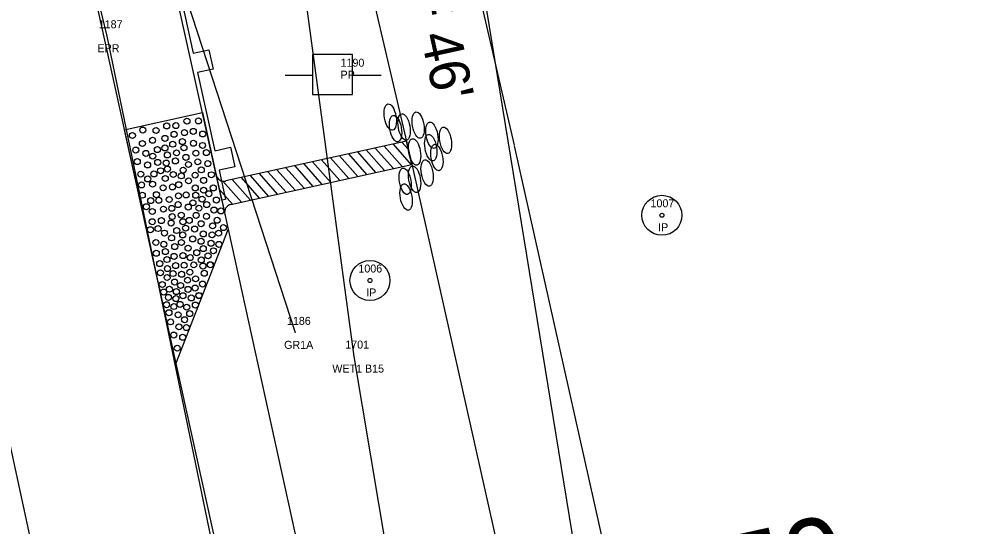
# Model space of a CAD drawing. Extents: x 2521558 to 2525396, y 882711 to 887632.
# Drawn here: x 2523806.5 to 2523924.8, y 884989.6 to 885053.1 of the extents above; entities that cross this region are included whole.
import ezdxf

# ---------------------------------------------------------------- set-up
doc = ezdxf.new("R2010")
doc.units = 0
for name, color, linetype in [('RD_EV_JurisArea', 7, 'Continuous'), ('RD_EX_DV_Prop_txCode', 7, 'Continuous'), ('RD_EX_DV_PropPin', 7, 'Continuous'), ('RD_EX_GuardRail', 7, 'Continuous'), ('RD_EX_GuardRail_txCode', 7, 'Continuous'), ('RD_EX_H2O_WetLd_txCode', 7, 'Continuous'), ('RD_EX_Road', 7, 'Continuous'), ('RD_EX_Road_txCode', 7, 'Continuous'), ('RD_EX_RW_TX', 7, 'Continuous'), ('RD_EX_UT', 7, 'Continuous'), ('RD_EX_UT_txCode', 7, 'Continuous'), ('RD_EX_VEG', 7, 'Continuous'), ('RD_PD_Bridge', 7, 'Continuous'), ('RD_PD_CstnLmt', 7, 'Continuous'), ('RD_PD_DR_ErosCtrl', 7, 'Continuous'), ('RD_PD_Final_TrvlWay', 7, 'Continuous'), ('RD_PD_GR', 7, 'Continuous'), ('RD_PD_PaveShd', 7, 'Continuous'), ('RD_SMD_Locator', 7, 'Continuous')]:
    doc.layers.add(name, color=color, linetype=linetype)

# ---------------------------------------------------------------- blocks, each defined once
blk = doc.blocks.new('TBC1')
at = {"layer": 'RD_PD_GR'}
blk.add_lwpolyline([(12.5, 2.5), (15, 2.5), (15, 0.49), (25, 0.49), (25, 2.5), (27.5, 2.5), (27.5, 0.49), (31.25, 0.49), (31.25, 0), (0, 0), (0, 0.49), (12.5, 0.49)], close=True, dxfattribs=at)

msp = doc.modelspace()

# ---------------------------------------------------------------- linework, layer by layer
at = {"layer": 'RD_EV_JurisArea'}
msp.add_lwpolyline([(2523944.86, 884550.08), (2523910.41, 884709.58), (2523888.01, 884815.03), (2523863.93, 884918.37), (2523848.43, 885010.84), (2523837.07, 885095.13), (2523817.82, 885104.47)], dxfattribs=at)
at = {"layer": 'RD_EX_DV_PropPin'}
for centre, radius in [((2523886.89, 885028.52), 2.5), ((2523886.89, 885028.52), 0.25), ((2523850.41, 885020.36), 2.5), ((2523850.41, 885020.36), 0.25)]:
    msp.add_circle(centre, radius, dxfattribs=at)
at = {"layer": 'RD_EX_GuardRail'}
msp.add_lwpolyline([(2523841.11, 885013.81), (2523827.6, 885055.26), (2523819.28, 885089.09)], dxfattribs=at)
at = {"layer": 'RD_EX_Road'}
for p, q in [((2523817.58, 885050.92), (2523809.38, 885084.88)), ((2523837.97, 884952.46), (2523817.58, 885050.92)), ((2523817, 884946.3), (2523795.47, 885045.91))]:
    msp.add_line(p, q, dxfattribs=at)
at = {"layer": 'RD_EX_UT'}
for p, q in [((2523848.22, 885048.62), (2523843.22, 885048.62)), ((2523843.22, 885048.62), (2523843.22, 885043.62)), ((2523848.22, 885043.62), (2523848.22, 885048.62)), ((2523839.79, 885046.06), (2523843.26, 885046.06)), ((2523848.15, 885046.06), (2523851.79, 885046.06)), ((2523843.22, 885043.62), (2523848.22, 885043.62))]:
    msp.add_line(p, q, dxfattribs=at)
at = {"layer": 'RD_EX_VEG'}
msp.add_lwpolyline([(2523998.75, 884575.96), (2523966.17, 884559.06), (2523924.93, 884771.45), (2523880.33, 884960.16), (2523862.36, 885070.56)], dxfattribs=at)
at = {"layer": 'RD_PD_CstnLmt'}
for p, q in [((2523844.92, 885081.02), (2523855.75, 885034.37)), ((2523855.75, 885034.37), (2523877.61, 884936.78))]:
    msp.add_line(p, q, dxfattribs=at)
at = {"layer": 'RD_PD_DR_ErosCtrl'}
for p, q in [((2523857.58, 885083.96), (2523868.41, 885037.31)), ((2523868.44, 885037.21), (2523890.29, 884939.62))]:
    msp.add_line(p, q, dxfattribs=at)
at = {"layer": 'RD_PD_Final_TrvlWay'}
msp.add_line((2523720.24, 885490.91), (2524037.44, 884050.42), dxfattribs=at)
at = {"layer": 'RD_PD_GR'}
msp.add_line((2523831.88, 885030.39), (2523990.48, 884310.15), dxfattribs=at)
at = {"layer": 'RD_PD_PaveShd'}
for p, q in [((2523819.7, 885039.23), (2523829.47, 885041.38)), ((2523829.47, 885041.38), (2523831.4, 885032.59)), ((2523819.7, 885039.23), (2523826.15, 885009.93)), ((2523854.96, 885037.79), (2523832.38, 885032.81)), ((2523853.3, 885037.42), (2523855.57, 885034.85)), ((2523853.3, 885037.42), (2523855.57, 885034.85)), ((2523854.41, 885037.67), (2523855.19, 885036.8)), ((2523855.63, 885034.87), (2523854.96, 885037.79)), ((2523847.71, 885036.19), (2523849.99, 885033.62)), ((2523847.71, 885036.19), (2523849.99, 885033.62)), ((2523848.83, 885036.44), (2523851.1, 885033.87)), ((2523848.83, 885036.44), (2523851.1, 885033.87)), ((2523849.95, 885036.69), (2523852.22, 885034.11)), ((2523849.95, 885036.69), (2523852.22, 885034.11)), ((2523851.06, 885036.93), (2523853.34, 885034.36)), ((2523851.06, 885036.93), (2523853.34, 885034.36)), ((2523852.18, 885037.18), (2523854.45, 885034.61)), ((2523852.18, 885037.18), (2523854.45, 885034.61)), ((2523833.02, 885029.88), (2523855.63, 885034.87)), ((2523842.13, 885034.96), (2523844.4, 885032.39)), ((2523842.13, 885034.96), (2523844.4, 885032.39)), ((2523843.24, 885035.21), (2523845.52, 885032.64)), ((2523843.24, 885035.21), (2523845.52, 885032.64)), ((2523844.36, 885035.45), (2523846.64, 885032.88)), ((2523844.36, 885035.45), (2523846.64, 885032.88)), ((2523845.48, 885035.7), (2523847.75, 885033.13)), ((2523845.48, 885035.7), (2523847.75, 885033.13)), ((2523846.6, 885035.95), (2523848.59, 885033.69)), ((2523846.6, 885035.95), (2523848.87, 885033.38)), ((2523836.54, 885033.73), (2523838.82, 885031.16)), ((2523837.66, 885033.97), (2523839.93, 885031.4)), ((2523837.66, 885033.97), (2523839.93, 885031.4)), ((2523838.78, 885034.22), (2523841.05, 885031.65)), ((2523838.78, 885034.22), (2523841.05, 885031.65)), ((2523839.89, 885034.47), (2523842.17, 885031.9)), ((2523839.89, 885034.47), (2523842.17, 885031.9)), ((2523841.01, 885034.71), (2523843.28, 885032.14)), ((2523841.01, 885034.71), (2523843.28, 885032.14)), ((2523831.4, 885032.59), (2523832.05, 885029.66)), ((2523832.03, 885032.79), (2523834.35, 885030.17)), ((2523833.19, 885032.99), (2523835.46, 885030.42)), ((2523833.19, 885032.99), (2523835.46, 885030.42)), ((2523834.31, 885033.23), (2523836.58, 885030.66)), ((2523834.31, 885033.23), (2523836.58, 885030.66)), ((2523835.43, 885033.48), (2523837.7, 885030.91)), ((2523835.43, 885033.48), (2523837.7, 885030.91)), ((2523831.58, 885031.79), (2523833.23, 885029.92)), ((2523832.05, 885029.66), (2523832.69, 885026.73)), ((2523826.15, 885009.93), (2523832.69, 885026.73))]:
    msp.add_line(p, q, dxfattribs=at)
for centre in [(2523825, 885039.7), (2523825, 885039.7), (2523826.15, 885039.74), (2523826.15, 885039.74), (2523827.53, 885040.3), (2523827.53, 885040.3), (2523828.97, 885040.32), (2523828.97, 885040.32), (2523828.97, 885040.32), (2523820.72, 885038.5), (2523820.72, 885038.5), (2523822.02, 885039.18), (2523822.02, 885039.18), (2523823.67, 885039.13), (2523823.67, 885039.13), (2523824.79, 885038.14), (2523824.79, 885038.14), (2523825.92, 885038.66), (2523825.92, 885038.66), (2523827.22, 885038.86), (2523827.22, 885038.86), (2523828.33, 885039.02), (2523828.33, 885039.02), (2523829.51, 885038.69), (2523829.51, 885038.69), (2523821.97, 885037.5), (2523821.97, 885037.5), (2523823.23, 885037.9), (2523823.23, 885037.9), (2523824.78, 885036.95), (2523824.78, 885036.95), (2523825.76, 885037.41), (2523825.76, 885037.41), (2523826.96, 885037.74), (2523826.96, 885037.74), (2523827.16, 885036.96), (2523827.16, 885036.96), (2523828.35, 885037.53), (2523828.35, 885037.53), (2523829.48, 885037.26), (2523829.48, 885037.26), (2523821.14, 885036.68), (2523821.14, 885036.68), (2523822.4, 885036.26), (2523822.4, 885036.26), (2523823.26, 885035.92), (2523823.26, 885035.92), (2523823.84, 885036.74), (2523823.84, 885036.74), (2523825.09, 885036.07), (2523825.09, 885036.07), (2523826.23, 885036.33), (2523826.23, 885036.33), (2523827.41, 885035.77), (2523827.41, 885035.77), (2523828.65, 885036.29), (2523828.65, 885036.29), (2523829.96, 885036.36), (2523829.96, 885036.36), (2523821.33, 885035.24), (2523821.33, 885035.24), (2523822.62, 885034.82), (2523822.62, 885034.82), (2523823.88, 885035.14), (2523823.88, 885035.14), (2523824.94, 885035.06), (2523826.09, 885035.32), (2523826.09, 885035.32), (2523827.72, 885034.88), (2523827.72, 885034.88), (2523828.89, 885035.21), (2523828.89, 885035.21), (2523830.14, 885034.99), (2523830.14, 885034.99), (2523821.77, 885033.67), (2523821.77, 885033.67), (2523823.41, 885033.69), (2523823.41, 885033.69), (2523824.24, 885034.09), (2523824.24, 885034.09), (2523825.1, 885034.31), (2523825.1, 885034.31), (2523825.83, 885033.62), (2523825.83, 885033.62), (2523826.82, 885033.45), (2523826.82, 885033.45), (2523827.06, 885034.17), (2523827.06, 885034.17), (2523828.56, 885033.54), (2523828.56, 885033.54), (2523829.33, 885034.2), (2523829.33, 885034.2), (2523830.59, 885033.59), (2523830.59, 885033.59), (2523821.86, 885032.32), (2523821.86, 885032.32), (2523822.63, 885033.07), (2523822.63, 885033.07), (2523823.24, 885032.41), (2523823.24, 885032.41), (2523824.83, 885033.12), (2523824.83, 885033.12), (2523826.5, 885032.35), (2523826.5, 885032.35), (2523827.73, 885032.83), (2523827.73, 885032.83), (2523829.62, 885032.89), (2523829.62, 885032.89), (2523821.95, 885031.03), (2523821.95, 885031.03), (2523823.72, 885031.09), (2523823.72, 885031.09), (2523824.56, 885031.96), (2523824.56, 885031.96), (2523825.72, 885032.06), (2523825.72, 885032.06), (2523826.47, 885030.95), (2523826.47, 885030.95), (2523827.43, 885031.06), (2523827.43, 885031.06), (2523828.58, 885031.94), (2523828.58, 885031.94), (2523828.63, 885031.02), (2523828.63, 885031.02), (2523829.62, 885031.66), (2523829.62, 885031.66), (2523830.27, 885031.22), (2523830.27, 885031.22), (2523830.82, 885031.94), (2523830.82, 885031.94), (2523823.01, 885030.35), (2523823.01, 885030.35), (2523824.02, 885030.4), (2523824.02, 885030.4), (2523825.32, 885030.49), (2523825.32, 885030.49), (2523826.43, 885029.86), (2523826.43, 885029.86), (2523828.29, 885030.08), (2523828.29, 885030.08), (2523829.42, 885030.54), (2523829.42, 885030.54), (2523830, 885029.86), (2523830, 885029.86), (2523831.21, 885030.43), (2523831.21, 885030.43), (2523822.46, 885029.59), (2523823.2, 885028.99), (2523823.2, 885028.99), (2523824.6, 885029.29), (2523824.6, 885029.29), (2523825.64, 885029.39), (2523825.64, 885029.39), (2523827.7, 885029.55), (2523827.7, 885029.55), (2523829.02, 885029.41), (2523829.02, 885029.41), (2523830.91, 885029.18), (2523830.91, 885029.18), (2523831.77, 885029.06), (2523831.77, 885029.06), (2523823.19, 885027.72), (2523823.19, 885027.72), (2523824.34, 885027.85), (2523824.34, 885027.85), (2523825.56, 885027.55), (2523825.56, 885027.55), (2523825.69, 885028.36), (2523825.69, 885028.36), (2523826.83, 885028.54), (2523826.83, 885028.54), (2523827.03, 885027.72), (2523827.03, 885027.72), (2523827.83, 885027.88), (2523827.83, 885027.88), (2523828.68, 885028.51), (2523828.68, 885028.51), (2523829.31, 885027.46), (2523829.31, 885027.46), (2523829.97, 885028.4), (2523829.97, 885028.4), (2523831.31, 885027.9), (2523831.31, 885027.9), (2523822.96, 885026.72), (2523822.96, 885026.72), (2523823.92, 885026.86), (2523823.92, 885026.86), (2523824.72, 885026.29), (2523824.72, 885026.29), (2523826.26, 885026.61), (2523826.26, 885026.61), (2523827.37, 885026.91), (2523827.37, 885026.91), (2523828.49, 885026.8), (2523828.49, 885026.8), (2523830.74, 885027.2), (2523830.74, 885027.2), (2523831.49, 885026.28), (2523831.49, 885026.28), (2523832.1, 885026.98), (2523832.1, 885026.98), (2523832.1, 885026.98), (2523823.65, 885025.11), (2523823.65, 885025.11), (2523825.62, 885025.69), (2523825.62, 885025.69), (2523826.84, 885025.12), (2523826.84, 885025.12), (2523827.01, 885026.06), (2523827.01, 885026.06), (2523828.25, 885025.56), (2523828.25, 885025.56), (2523829.3, 885025.27), (2523829.3, 885025.27), (2523829.58, 885026.18), (2523829.58, 885026.18), (2523830.55, 885025.02), (2523830.55, 885025.02), (2523830.67, 885026.08), (2523830.67, 885026.08), (2523824.64, 885024.89), (2523824.64, 885024.89), (2523824.84, 885023.97), (2523824.84, 885023.97), (2523826, 885024.6), (2523826, 885024.6), (2523827.67, 885024.41), (2523827.67, 885024.41), (2523828.76, 885023.84), (2523828.76, 885023.84), (2523829.58, 885024.35), (2523829.58, 885024.35), (2523830.85, 885024.08), (2523830.85, 885024.08), (2523831.52, 885024.88), (2523831.52, 885024.88), (2523823.7, 885023.76), (2523823.7, 885023.76), (2523825.03, 885022.98), (2523825.03, 885022.98), (2523825.92, 885023.38), (2523825.92, 885023.38), (2523827.03, 885023.47), (2523827.03, 885023.47), (2523827.94, 885023.22), (2523827.94, 885023.22), (2523829.32, 885022.94), (2523829.32, 885022.94), (2523830.17, 885023.45), (2523830.17, 885023.45), (2523824.13, 885022.47), (2523824.13, 885022.47), (2523825.1, 885021.85), (2523825.1, 885021.85), (2523826.12, 885022.22), (2523826.12, 885022.22), (2523827.18, 885022.27), (2523827.18, 885022.27), (2523828.39, 885022.32), (2523828.39, 885022.32), (2523829.53, 885022.17), (2523829.53, 885022.17), (2523830.44, 885022.32), (2523830.45, 885022.33), (2523824.22, 885021.32), (2523824.22, 885021.32), (2523825.06, 885020.73), (2523825.06, 885020.73), (2523825.8, 885021.23), (2523825.8, 885021.23), (2523826.87, 885021.14), (2523826.87, 885021.14), (2523827.61, 885020.4), (2523827.61, 885020.4), (2523827.9, 885021.4), (2523827.9, 885021.4), (2523828.62, 885020.57), (2523828.62, 885020.57), (2523829.7, 885021.26), (2523829.7, 885021.26), (2523824.45, 885019.86), (2523824.45, 885019.86), (2523825.34, 885019.27), (2523825.34, 885019.27), (2523825.98, 885020.17), (2523825.98, 885020.17), (2523826.74, 885019.74), (2523826.74, 885019.74), (2523827.67, 885019.25), (2523827.67, 885019.25), (2523828.56, 885019.42), (2523828.56, 885019.42), (2523829.48, 885019.92), (2523829.48, 885019.92), (2523824.63, 885018.91), (2523824.63, 885018.91), (2523825.22, 885018.25), (2523825.22, 885018.25), (2523826.15, 885018.09), (2523826.15, 885018.09), (2523826.21, 885018.97), (2523826.21, 885018.97), (2523827.04, 885018.46), (2523827.04, 885018.46), (2523828.07, 885018.18), (2523828.07, 885018.18), (2523829.02, 885018.46), (2523829.04, 885018.49), (2523824.98, 885017.33), (2523824.98, 885017.33), (2523825.9, 885017.1), (2523825.9, 885017.1), (2523826.67, 885017.37), (2523826.67, 885017.37), (2523827.51, 885017.02), (2523827.51, 885017.02), (2523828.59, 885017.29), (2523828.59, 885017.29), (2523825.29, 885016.33), (2523825.29, 885016.33), (2523826.43, 885016.07), (2523826.43, 885016.07), (2523827.88, 885016.22), (2523825.48, 885015.18), (2523825.48, 885015.18), (2523826.53, 885014.56), (2523826.53, 885014.56), (2523827.23, 885015.45), (2523827.23, 885015.45), (2523827.47, 885014.47), (2523827.47, 885014.47), (2523825.89, 885013.54), (2523825.89, 885013.54), (2523827, 885013.26), (2523827, 885013.26), (2523826.32, 885011.89)]:
    msp.add_circle(centre, 0.375, dxfattribs=at)
for centre, start, end in [((2523832.16, 885033.78), 192.4185, 282.4481), ((2523833.24, 885028.9), 102.4481, 192.4185)]:
    msp.add_arc(centre, 1, start, end, dxfattribs=at)
for centre in [(2523852.95, 885040.8), (2523852.95, 885040.8), (2523853.61, 885039.37), (2523853.61, 885039.37), (2523854.67, 885039.57), (2523854.67, 885039.57), (2523856.43, 885039.8), (2523856.43, 885039.8), (2523858.15, 885038.54), (2523858.15, 885038.54), (2523859.85, 885037.9), (2523859.85, 885037.9), (2523858, 885036.98), (2523858, 885036.98), (2523855.99, 885036.45), (2523855.99, 885036.45), (2523858.77, 885035.75), (2523858.77, 885035.75), (2523857.55, 885033.81), (2523857.55, 885033.81), (2523854.81, 885032.78), (2523855.99, 885033.03), (2523855.99, 885033.03), (2523854.92, 885030.8)]:
    msp.add_ellipse(centre, major_axis=(0.29, -1.65), ratio=0.429445, dxfattribs=at)
at = {"layer": 'RD_SMD_Locator'}
for centre in [(2523817.58, 885050.92), (2523847.39, 885029.23), (2523841.11, 885013.81), (2523848.43, 885010.84)]:
    msp.add_circle(centre, 0.001, dxfattribs=at)

# ---------------------------------------------------------------- block references
at = {"layer": 'RD_PD_Bridge', "rotation": -77.58151740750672}
msp.add_blockref('TBC1', (2523825.16, 885060.91), dxfattribs=at)

# ---------------------------------------------------------------- texts
at = {"layer": 'RD_EX_DV_Prop_txCode'}
for s, p in [('1007', (2523885.47, 885029.52)), ('IP', (2523886.42, 885026.52)), ('1006', (2523848.96, 885021.36)), ('IP', (2523849.94, 885018.36))]:
    msp.add_text(s, height=1, dxfattribs=at).set_placement(p)
at = {"layer": 'RD_EX_GuardRail_txCode'}
for s, p in [('1186', (2523840.03, 885014.81)), ('GR1A', (2523839.68, 885011.81))]:
    msp.add_text(s, height=1, dxfattribs=at).set_placement(p)
at = {"layer": 'RD_EX_H2O_WetLd_txCode'}
for s, p in [('1701', (2523847.32, 885011.84)), ('WET1 B15', (2523845.7, 885008.84))]:
    msp.add_text(s, height=1, dxfattribs=at).set_placement(p)
at = {"layer": 'RD_EX_Road_txCode'}
for s, p in [('1187', (2523816.51, 885051.92)), ('EPR', (2523816.35, 885048.92))]:
    msp.add_text(s, height=1, dxfattribs=at).set_placement(p)
at = {"layer": 'RD_EX_RW_TX'}
msp.add_text('+50', height=10, rotation=12.4185, dxfattribs=at).set_placement((2523888.56, 884976.64))
at = {"layer": 'RD_EX_UT_txCode'}
for s, p in [('1190', (2523846.73, 885047.11)), ('PP', (2523846.73, 885045.61))]:
    msp.add_text(s, height=1, dxfattribs=at).set_placement(p)
at = {"layer": 'RD_PD_CstnLmt'}
msp.add_text("F 46'", height=5, rotation=282.4185, dxfattribs=at).set_placement((2523855.43, 885056.8))

doc.saveas('drawing.dxf')
